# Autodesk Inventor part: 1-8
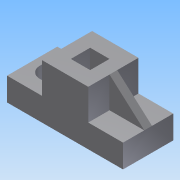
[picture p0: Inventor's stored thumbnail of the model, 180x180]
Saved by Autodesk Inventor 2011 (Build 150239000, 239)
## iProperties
Created: 2014-02
Part Number: 1-8
Document SubType Name: Modeling
Designer: Administrator
Density: 1 g/cm^3
Author: Administrator
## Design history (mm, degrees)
sketch "草图1"
  geometry: L1 (-15, 6.5)-(15, 6.5); L2 (15, 6.5)-(15, -6.5); L3 (15, -6.5)-(-15, -6.5); L4 (-15, -6.5)-(-15, 6.5); 3 further points
  constraints: 8 end point, 2 midpoint, 2 parallel, 1 horizontal, 1 horizontal alignment, 1 perpendicular, 1 vertical alignment
extrude "拉伸1" new body sketch "草图1" distance "d0" = 6; taper "d1" = 0 deg
sketch "草图2"
  geometry: L1 (-15, 6.5)-(15, 6.5) reference; L2 (15, -6.5)-(-15, -6.5) reference; L3 (-6, 6.5)-(6, 6.5); L4 (6, 6.5)-(6, -6.5); L5 (6, -6.5)-(-6, -6.5); L6 (-6, -6.5)-(-6, 6.5); 2 further points
  constraints: 8 end point, 2 parallel, 2 point on line, 1 horizontal, 1 midpoint, 1 perpendicular, 1 vertical alignment
  dimensions: "d2" = 12 distance of L4.end L5.end
extrude "拉伸2" join sketch "草图2" distance "d3" = 8; taper "d4" = 0 deg
sketch "草图3"
  geometry: L1 (-2.5, -2.5)-(2.5, -2.5); L2 (2.5, -2.5)-(2.5, 2.5); L3 (2.5, 2.5)-(-2.5, 2.5); L4 (-2.5, 2.5)-(-2.5, -2.5); 3 further points
  constraints: 8 end point, 2 midpoint, 2 parallel, 1 horizontal, 1 horizontal alignment, 1 perpendicular, 1 vertical alignment
  dimensions: "d14" = 5 distance of L1.end L2.end; "d15" = 5 distance of L1.start L1.end
extrude "拉伸3" cut sketch "草图3" stored distance "d5" = 8; taper "d6" = 0 deg
sketch "草图4"
  geometry: L1 (-2.5, -2.5)-(-2.5, 2.5) reference; L2 (-2.5, 2.5)-(2.5, 2.5) reference; L3 (2.5, 2.5)-(2.5, -2.5) reference; L4 (2.5, -2.5)-(-2.5, -2.5) reference; L5 (-4, -4)-(4, -4); L6 (4, -4)-(4, 4); L7 (4, 4)-(-4, 4); L8 (-4, 4)-(-4, -4); 1 further point
  constraints: 8 end point, 2 parallel, 1 horizontal, 1 perpendicular
extrude "拉伸4" cut sketch "草图4" distance "d7" = 2; taper "d8" = 0 deg
sketch "草图5"
  geometry: C1 r 3 at (-10, 0); 1 further point
  constraints: 1 centre point
  dimensions: "d9" = 6 diameter of C1
extrude "拉伸5" cut sketch "草图5" stored distance "d10" = 2; taper "d11" = 0 deg
sketch "草图6"
  geometry: L1 (-6, 6)-(-6, 14) reference; L2 (-6, 6)-(-15, 6) reference; L3 (-6, 14)-(-15, 6); 1 further point
  constraints: 2 end point
extrude "拉伸6" join sketch "草图6" stored distance "d12" = 2; taper "d13" = 0 deg
node "实体1"
